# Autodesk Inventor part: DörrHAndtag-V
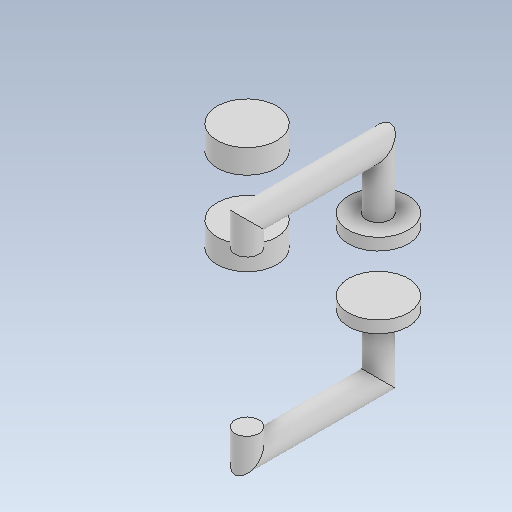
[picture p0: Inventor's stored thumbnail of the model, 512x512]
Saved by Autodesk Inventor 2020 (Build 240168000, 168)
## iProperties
Created: 2019-06
Part Number: DörrHAndtag-V
Material: Generic
Document SubType Name: Modeling
Designer: cl
Density: 1 g/cm^3
Appearance: Default
Author: cl
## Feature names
1. Extrusion1
2. Extrusion2
3. Sweep1
4. Mirror1
## Parameters: d3 = 0, d5 = 0, d8 = 0, d10 = 0, d15 = 0, d16 = 0, d17 = 25 mm
